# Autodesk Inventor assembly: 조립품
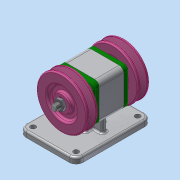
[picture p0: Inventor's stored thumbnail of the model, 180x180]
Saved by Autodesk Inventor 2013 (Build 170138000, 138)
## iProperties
Created: 2020-11
Part Number: 조립품
Document SubType Name: Assembly
Designer: user
Author: user
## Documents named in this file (10)
- C:\Users\user\Desktop\701106V1035\조립품.iam
- C:\Users\user\Desktop\701106V1035\본체.ipt
- C:\Users\user\Desktop\701106V1035\볼트 M4.ipt
- C:\Users\user\Desktop\701106V1035\축.ipt
- C:\Users\user\Desktop\701106V1035\V-벨트풀리.ipt
- C:\Users\user\Desktop\701106V1035\너트 M10x1.ipt
- C:\Users\user\Desktop\701106V1035\베어링 6004.ipt
- C:\Users\user\Desktop\701106V1035\오일 실 17 30 5.ipt
- C:\Users\user\Desktop\701106V1035\커버.ipt
- C:\Users\user\Desktop\701106V1035\키 5 x 5 x 12.ipt
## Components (2 placed, 1 different names)
1. V-벨트풀리:1
2. V-벨트풀리:2
## Component patterns: 구성요소 패턴 1:2 (2 elements), 구성요소 패턴 3:2 (2 elements)
